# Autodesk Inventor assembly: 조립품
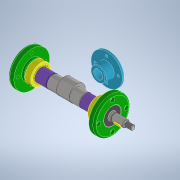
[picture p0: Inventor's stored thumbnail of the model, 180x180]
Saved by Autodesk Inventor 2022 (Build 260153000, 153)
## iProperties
Created: 2024-04
Part Number: 조립품
Document SubType Name: Assembly
Designer: Admin
Author: Admin
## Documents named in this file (11)
- C:\Users\Admin\Desktop\740406V1001\조립품.iam
- C:\Users\Admin\Desktop\740406V1001\본체.ipt
- C:\Users\Admin\Desktop\740406V1001\뒤커버.ipt
- C:\Users\Admin\Desktop\740406V1001\앞커버.ipt
- C:\Users\Admin\Desktop\740406V1001\베어링- 6202.ipt
- KS B 2023 - 6202 - 15 x 35 x 11 - 7.8.ipt
- C:\Users\Admin\Desktop\740406V1001\오일실 15 30 7.ipt
- C:\Users\Admin\Desktop\740406V1001\상부커버.ipt
- C:\Users\Admin\Desktop\740406V1001\칼라.ipt
- C:\Users\Admin\Desktop\740406V1001\편심축.ipt
- C:\Users\Admin\Desktop\740406V1001\키 4 x 4 x 12.ipt
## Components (2 placed, 1 different names)
1. KS B 2023 - 6202 - 15 x 35 x 11 - 7.8:2
2. KS B 2023 - 6202 - 15 x 35 x 11 - 7.8:3
